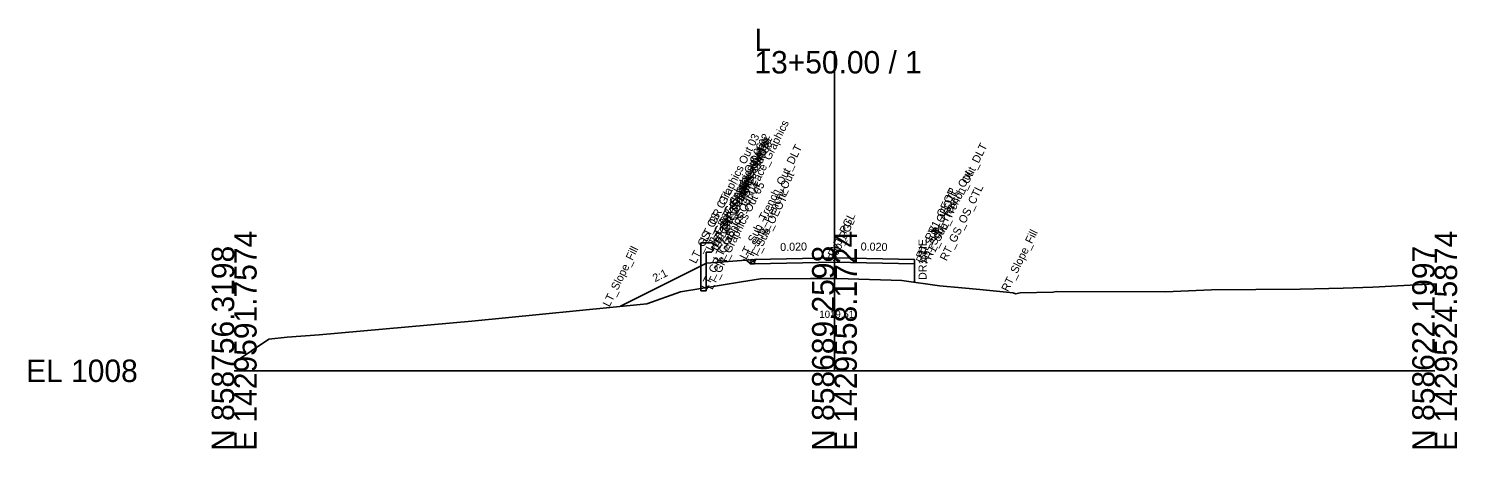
# Model space of a CAD drawing. Extents: x -26 to 153, y -10 to 13058.
# Drawn here: x -25.7 to 152.8, y 3990.3 to 4042.7 of the extents above; entities that cross this region are included whole.
import ezdxf

# ---------------------------------------------------------------- set-up
doc = ezdxf.new("R2010")
doc.units = 0
for name, color, linetype in [('Default', 7, 'Continuous'), ('Exist Cross Section Cell', 7, 'Continuous'), ('Exist XS Center Line Elevation Label', 7, 'Continuous'), ('Exist XS Ground Line', 7, 'Continuous'), ('Prop CMT Guardrail Graphics', 7, 'Continuous'), ('Prop CMT Pvmt Course 1', 7, 'Continuous'), ('Prop CMT Pvmt Surface', 7, 'Continuous'), ('Prop CMT Pvmt Surface Shoulder', 7, 'Continuous'), ('Prop CMT Shld Paved Course 1', 7, 'Continuous'), ('Prop CMT Slope Grass', 7, 'Continuous'), ('Prop CMT Subgrade Earthwork', 7, 'Continuous'), ('Prop XS Dump Level', 7, 'Continuous'), ('Prop XS SE Text', 7, 'Continuous'), ('Prop XS Side Slope Text', 7, 'Continuous'), ('Prop XSC Text', 7, 'Continuous')]:
    doc.layers.add(name, color=color, linetype=linetype)

msp = doc.modelspace()

# ---------------------------------------------------------------- linework, layer by layer
at = {"layer": 'Exist Cross Section Cell'}
for p, q in [((75, 4000), (75, 4039.93)), ((0, 4000), (75, 4000)), ((75, 4000), (150, 4000))]:
    msp.add_line(p, q, dxfattribs=at)
at = {"layer": 'Exist XS Ground Line'}
msp.add_lwpolyline([(0, 4001.03), (4.32, 4003.94), (6.62, 4004.19), (10.62, 4004.49), (29.71, 4006.2), (51.57, 4008.38), (55.75, 4009.87), (63.39, 4011.1), (65.78, 4011.47), (72.01, 4011.51), (74.2, 4011.52), (75, 4011.51), (76.73, 4011.49), (83.44, 4011.29), (88.12, 4010.63), (90.9, 4010.38), (93.17, 4010.15), (97.32, 4009.74), (97.62, 4009.61), (98.19, 4009.73), (102.31, 4009.81), (102.72, 4009.92), (116.38, 4009.86), (122.13, 4010.13), (133.17, 4010.2), (138.57, 4010.3), (142.28, 4010.46), (150, 4010.86)], dxfattribs=at)
at = {"layer": 'Prop CMT Guardrail Graphics'}
for points in [[(58.32, 4009.99), (58.32, 4015.99)], [(58.32, 4015.99), (59.65, 4015.99), (59.92, 4015.7)], [(59.92, 4015.7), (59.65, 4015.41)], [(59.65, 4015.41), (59.92, 4015.12)], [(59.92, 4015.12), (59.65, 4014.82), (58.98, 4014.82)], [(58.98, 4014.82), (58.98, 4009.99)], [(58.98, 4009.99), (58.32, 4009.99)]]:
    msp.add_lwpolyline(points, dxfattribs=at)
at = {"layer": 'Prop CMT Pvmt Course 1'}
for points in [[(75, 4014.1), (65, 4013.9)], [(65, 4013.9), (65, 4013.36)], [(65, 4013.36), (75, 4013.56)], [(75, 4013.56), (75, 4014.1)], [(75, 4014.1), (85, 4013.9)], [(75, 4013.56), (75, 4014.1)], [(85, 4013.36), (75, 4013.56)], [(85, 4013.9), (85, 4013.36)]]:
    msp.add_lwpolyline(points, dxfattribs=at)
at = {"layer": 'Prop CMT Pvmt Surface'}
for points in [[(75, 4014.1), (65, 4013.9)], [(75, 4014.1), (85, 4013.9)]]:
    msp.add_lwpolyline(points, dxfattribs=at)
at = {"layer": 'Prop CMT Pvmt Surface Shoulder'}
msp.add_lwpolyline([(65, 4013.9), (65, 4013.9)], dxfattribs=at)
at = {"layer": 'Prop CMT Shld Paved Course 1'}
for points in [[(65, 4013.9), (64.45, 4013.34)], [(65, 4013.9), (65, 4013.9)], [(65, 4013.36), (65, 4013.9)], [(85, 4013.36), (85, 4013.9)], [(64.45, 4013.34), (65, 4013.36)]]:
    msp.add_lwpolyline(points, dxfattribs=at)
at = {"layer": 'Prop CMT Slope Grass'}
msp.add_lwpolyline([(65, 4013.9), (59, 4013.42), (48.27, 4008.05)], dxfattribs=at)
at = {"layer": 'Prop CMT Subgrade Earthwork'}
for points in [[(64.45, 4013.34), (63.98, 4013.82)], [(75, 4013.56), (65, 4013.36)], [(75, 4013.56), (85, 4013.36)], [(65, 4013.36), (64.45, 4013.34)]]:
    msp.add_lwpolyline(points, dxfattribs=at)
at = {"layer": 'Prop XSC Text'}
msp.add_line((85, 4013.36), (85, 4011.07), dxfattribs=at)

# ---------------------------------------------------------------- texts
at = {"layer": 'Default'}
msp.add_text('-', height=0.0001, dxfattribs=at).set_placement((0, 4000))
at = {"layer": 'Exist Cross Section Cell'}
for s, p in [('L', (65, 4039.93)), ('13+50.00 / 1', (65, 4037.13)), ('EL 1008', (-26, 3998.6))]:
    msp.add_text(s, height=2.8, dxfattribs=at).set_placement(p)
for s, p in [('E 1429591.7574', (2.8, 3990)), ('E 1429558.1724', (77.8, 3990)), ('E 1429524.5874', (152.8, 3990)), ('N 858756.3198', (0, 3990)), ('N 858689.2598', (75, 3990)), ('N 858622.1997', (150, 3990))]:
    msp.add_text(s, height=2.8, rotation=90, dxfattribs=at).set_placement(p)
at = {"layer": 'Exist XS Center Line Elevation Label'}
msp.add_text('1019.51', height=0.9, dxfattribs=at).set_placement((73.11, 4006.61))
msp.add_text('1019.51', height=0.9, dxfattribs=at).set_placement((73.11, 4006.61))
msp.add_text('1019.51', height=0.9, dxfattribs=at).set_placement((73.11, 4006.61))
at = {"layer": 'Prop XS Dump Level'}
for s, p in [('LT_GR_Graphics Out 03', (59.08, 4016.05)), ('LT_GR_Graphics Out 02', (60.41, 4016.05)), ('LT_GS_OS_GR_Face_Graphics', (60.68, 4013.55)), ('LT_GR_Graphics Out 06', (59.74, 4014.88)), ('LT_GR_Graphics Out 09', (60.41, 4015.47)), ('LT_GR_Graphics Out 07', (60.41, 4014.88)), ('LT_GR_Graphics Out 01', (60.68, 4015.76)), ('LT_GR_Graphics Out 08', (60.68, 4015.18)), ('LT_Sub_Trench_Out_DLT', (63.98, 4013.82)), ('RT_Sub_Trench_Out_DLT', (87.03, 4013.79)), ('LT_Sub_Trench_Out', (64.45, 4013.34)), ('RT_Sub_Trench_Out', (86.56, 4013.32)), ('LT_GS_OS_CTL', (57.68, 4013.31)), ('LT_GR_Graphics Out 04', (59.08, 4010.05)), ('LT_GR_Graphics Out 05', (59.74, 4010.05)), ('LT_PV1_OEOT', (65, 4013.9)), ('LT_PS1_OEOP', (65, 4013.9)), ('RT_PV1_OEOT', (86.01, 4013.88)), ('RT_PS1_OEOP', (86.01, 4013.88)), ('RT_GS_OS_CTL', (89.01, 4013.64)), ('RT_GS_OS_CTL', (89.01, 4013.64)), ('LT_Sub_OEOT', (65, 4013.36)), ('RT_Sub_OEOT', (86.01, 4013.34)), ('PV1_PGL', (75, 4014.1)), ('Sub_PGL', (75, 4013.56)), ('RT_Slope_Fill', (96.69, 4009.8)), ('RT_Slope_Fill', (96.69, 4009.8)), ('LT_Slope_Fill', (46.88, 4007.91))]:
    msp.add_text(s, height=1, rotation=63.5833, dxfattribs=at).set_placement(p)
at = {"layer": 'Prop XS SE Text'}
for rotation, p in [(1.1458, (68.23, 4014.96)), (358.8542, (78.27, 4015.03))]:
    msp.add_text('0.020', height=1, rotation=rotation, dxfattribs=at).set_placement(p)
at = {"layer": 'Prop XS Side Slope Text'}
msp.add_text('2:1', height=1, rotation=26.5651, dxfattribs=at).set_placement((52.59, 4011.05))
at = {"layer": 'Prop XSC Text'}
msp.add_text('DR1 TIE', height=1, rotation=90, dxfattribs=at).set_placement((86.51, 4011.34))

doc.saveas('drawing.dxf')
